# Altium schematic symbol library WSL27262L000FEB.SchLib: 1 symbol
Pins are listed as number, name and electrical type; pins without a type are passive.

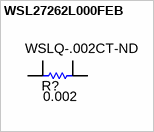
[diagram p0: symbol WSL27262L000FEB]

## WSL27262L000FEB
designator R?  ValueDisplayed: 0.002  Supplier Part Number: WSLQ-.002CT-ND  (hidden comment: WSL27262L000FEB)
RES, 0.002, 1%, 3 W, 6.6x3x6.9mm; Manufacturer: Vishay Dale; CompType: Resistor; Value: 0.002; Res_ohm: 0.001; Value_Code: 1L000; Power_W: 3W; TempCo: ±75ppm/°C; EIA_Code: E96; U/M: EA; Description: RES .002 OHM 3W 1% 2726 SMD
signal-integrity model Resistor
simulation model Resistor
footprint RES_WSL2726
footprint RES_WSL2726 WITH VIAS (Vishay Dale)
pins: 1, 2, 3, 4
